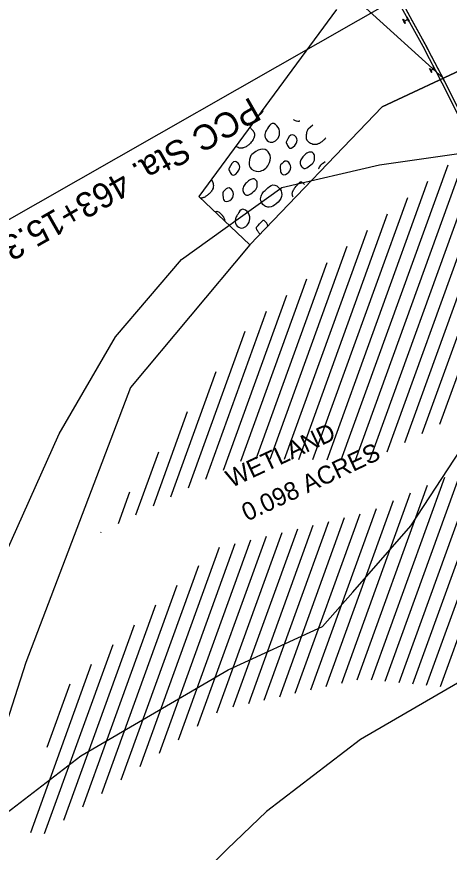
# Model space of a CAD drawing. Extents: x 2355002 to 2355569, y 708374 to 709566.
# Drawn here: x 2355270.5 to 2355318.9, y 709251.3 to 709344.6 of the extents above; entities that cross this region are included whole.
import ezdxf

# ---------------------------------------------------------------- set-up
doc = ezdxf.new("R2010")
doc.units = 0
for name, color, linetype in [('BD_X_Building', 7, 'Continuous'), ('BR_X_Rail_Stl_Det', 7, 'Continuous'), ('BR_X_Slab_Object', 7, 'Continuous'), ('DR_X_Ditch', 7, 'Continuous'), ('HY_X_Water_Edge', 7, 'Continuous'), ('HY_X_Wetland_Area', 7, 'Continuous'), ('PM_X_Edge_Line', 7, 'Continuous'), ('PM_X_Stop_Line', 7, 'Continuous'), ('RD_X_Concrete_Pad', 7, 'Continuous'), ('RD_X_RR_Cells', 7, 'Continuous'), ('SH_Text', 7, 'Continuous'), ('VG_X_Tree_Line_Rt', 7, 'Continuous')]:
    doc.layers.add(name, color=color, linetype=linetype)

msp = doc.modelspace()

# ---------------------------------------------------------------- linework, layer by layer
at = {"layer": 'BR_X_Rail_Stl_Det'}
for points in [[(2355313.802, 709344.05), (2355313.679, 709344.271), (2355313.712, 709344.29), (2355313.815, 709344.106)], [(2355313.856, 709344.031), (2355313.959, 709343.847), (2355313.925, 709343.829), (2355313.802, 709344.05)], [(2355313.855, 709344.095), (2355314.201, 709344.287)], [(2355314.214, 709344.264), (2355313.868, 709344.071)], [(2355314.213, 709344.328), (2355314.111, 709344.511), (2355314.144, 709344.53), (2355314.39, 709344.087), (2355314.357, 709344.068), (2355314.255, 709344.252)], [(2355316.76, 709338.56), (2355316.643, 709338.785), (2355316.676, 709338.802), (2355316.774, 709338.616)], [(2355316.813, 709338.539), (2355316.911, 709338.353), (2355316.877, 709338.335), (2355316.76, 709338.56)], [(2355316.814, 709338.603), (2355317.165, 709338.787)], [(2355317.177, 709338.763), (2355316.826, 709338.58)], [(2355317.178, 709338.827), (2355317.08, 709339.013), (2355317.114, 709339.031), (2355317.348, 709338.582), (2355317.315, 709338.564), (2355317.218, 709338.75)]]:
    msp.add_lwpolyline(points, dxfattribs=at)
for centre, radius, start, end in [((2355104.75, 709227.887), 239.69, 6.23645, 29.69194), ((2355104.75, 709227.887), 240.024, 6.23645, 29.69194), ((2355313.841, 709344.121), 0.0298, 209.0594, 299.0594), ((2355313.882, 709344.045), 0.0298, 119.0594, 209.0594), ((2355314.187, 709344.313), 0.0298, 299.0594, 29.0594), ((2355314.229, 709344.238), 0.0298, 29.0594, 119.0594), ((2355316.8, 709338.63), 0.0298, 207.56539, 297.56539), ((2355316.84, 709338.553), 0.0298, 117.56539, 207.56539), ((2355317.151, 709338.813), 0.0298, 297.56539, 27.56539), ((2355317.191, 709338.737), 0.0298, 27.56539, 117.56539)]:
    msp.add_arc(centre, radius, start, end, dxfattribs=at)
at = {"layer": 'BR_X_Slab_Object'}
msp.add_arc((2355104.75, 709227.887), 240.024, 6.69347, 29.69206, dxfattribs=at)
at = {"layer": 'DR_X_Ditch'}
msp.add_lwpolyline([(2355256.934, 709256.527), (2355268.599, 709283.201), (2355275.266, 709297.997), (2355281.566, 709308.847), (2355288.953, 709317.469), (2355300.165, 709325.51), (2355311.07, 709328.057), (2355320.733, 709329.426)], dxfattribs=at)
at = {"layer": 'HY_X_Water_Edge'}
for points in [[(2355250.911, 709219.998), (2355253.586, 709233.349), (2355257.951, 709241.6), (2355265.075, 709252.406), (2355277.693, 709262.077), (2355294.163, 709271.671), (2355304.717, 709276.5), (2355308.101, 709280.351), (2355314.576, 709287.749), (2355320.15, 709296.253), (2355326.599, 709303.193), (2355329.602, 709308.443), (2355330.306, 709308.794)], [(2355337.752, 709284.561), (2355335.596, 709283.025), (2355327.107, 709277.253), (2355320.964, 709270.848), (2355308.961, 709263.899), (2355298.457, 709255.856), (2355294.044, 709251.65), (2355284.365, 709241.954), (2355272.475, 709233.758), (2355267.361, 709225.229), (2355264.268, 709216.725)]]:
    msp.add_lwpolyline(points, dxfattribs=at)
at = {"layer": 'HY_X_Wetland_Area'}
msp.add_lwpolyline([(2355402.731, 709358.025), (2355392.727, 709358.151), (2355360.724, 709357.63), (2355311.362, 709334.527), (2355296.582, 709319.103), (2355283.234, 709303.179), (2355271.55, 709272.489), (2355265.075, 709252.406)], dxfattribs=at)
at = {"layer": 'PM_X_Edge_Line'}
msp.add_arc((2355104.75, 709227.886), 246.024, 5.4603, 29.69206, dxfattribs=at)
at = {"layer": 'PM_X_Stop_Line'}
msp.add_line((2355303.089, 709332.064), (2355303.619, 709332.506), dxfattribs=at)
msp.add_lwpolyline([(2355306.276, 709345.396), (2355290.879, 709324.489), (2355296.582, 709319.103), (2355311.362, 709334.527), (2355360.724, 709357.63), (2355392.727, 709358.151), (2355391.331, 709364.068), (2355355.637, 709368.498)], dxfattribs=at)
for points in [[(2355302.183, 709332.911), (2355302.123, 709332.899), (2355302.093, 709332.893), (2355302.063, 709332.889), (2355301.807, 709332.903), (2355301.551, 709333.043), (2355301.477, 709333.11)], [(2355296.581, 709332.232), (2355296.657, 709332.157), (2355296.732, 709332.076), (2355296.807, 709331.994), (2355296.879, 709331.913), (2355296.92, 709331.864), (2355296.957, 709331.815), (2355297.016, 709331.712), (2355297.084, 709331.501), (2355297.093, 709331.291), (2355297.077, 709331.19), (2355297.064, 709331.142), (2355297.049, 709331.094), (2355297.005, 709330.982), (2355296.953, 709330.871), (2355296.825, 709330.657), (2355296.661, 709330.453), (2355296.564, 709330.355), (2355296.511, 709330.307), (2355296.484, 709330.283), (2355296.456, 709330.259), (2355296.358, 709330.182), (2355296.259, 709330.115), (2355296.06, 709330.008), (2355295.86, 709329.934), (2355295.758, 709329.908), (2355295.707, 709329.899), (2355295.656, 709329.89), (2355295.401, 709329.905), (2355295.144, 709330.045), (2355295.041, 709330.141)], [(2355298.569, 709332.089), (2355299.078, 709332.66), (2355299.741, 709332.224), (2355299.882, 709331.395), (2355299.458, 709330.728), (2355298.845, 709330.571), (2355298.299, 709331.109), (2355298.337, 709331.717), (2355298.569, 709332.089)], [(2355305.073, 709331.055), (2355305.011, 709330.982), (2355304.948, 709330.913), (2355304.82, 709330.782), (2355304.554, 709330.563), (2355304.279, 709330.403), (2355304.139, 709330.348), (2355304.069, 709330.327), (2355304.033, 709330.319), (2355303.998, 709330.311), (2355303.939, 709330.302), (2355303.878, 709330.297), (2355303.752, 709330.302), (2355303.492, 709330.367), (2355303.24, 709330.51), (2355303.124, 709330.611), (2355303.07, 709330.669), (2355303.044, 709330.7), (2355303.031, 709330.716), (2355303.019, 709330.732), (2355302.99, 709330.773), (2355302.966, 709330.814), (2355302.93, 709330.896), (2355302.898, 709331.061), (2355302.902, 709331.226), (2355302.911, 709331.308), (2355302.921, 709331.39), (2355302.935, 709331.507), (2355302.951, 709331.625), (2355302.974, 709331.742), (2355303.008, 709331.856), (2355303.089, 709332.064)], [(2355300.661, 709330.65), (2355301.358, 709331.402), (2355301.772, 709331.113), (2355301.758, 709330.438), (2355301.014, 709329.905), (2355300.74, 709330.306), (2355300.645, 709330.528), (2355300.661, 709330.65)], [(2355296.683, 709329.066), (2355297.248, 709329.537), (2355298.303, 709329.74), (2355298.839, 709329.102), (2355298.672, 709328.063), (2355297.592, 709327.313), (2355296.612, 709327.734), (2355296.515, 709328.391), (2355296.602, 709328.857), (2355296.683, 709329.066)], [(2355302.262, 709328.606), (2355302.609, 709329.044), (2355303.105, 709329.404), (2355303.556, 709329.436), (2355303.79, 709329.097), (2355303.732, 709328.414), (2355303.266, 709327.931), (2355302.624, 709327.644), (2355302.286, 709327.962), (2355302.21, 709328.368), (2355302.262, 709328.606)], [(2355294.255, 709327.652), (2355294.952, 709328.403), (2355295.365, 709328.115), (2355295.351, 709327.44), (2355294.608, 709326.906), (2355294.333, 709327.308), (2355294.238, 709327.53), (2355294.255, 709327.652)], [(2355300.016, 709328.034), (2355300.66, 709328.458), (2355301.127, 709327.952), (2355300.942, 709327.215), (2355300.194, 709326.99), (2355299.99, 709327.438), (2355299.957, 709327.783), (2355300.016, 709328.034)], [(2355304.266, 709327.596), (2355304.29, 709327.648), (2355304.317, 709327.699), (2355304.346, 709327.75), (2355304.377, 709327.8), (2355304.522, 709328.012), (2355304.602, 709328.105), (2355304.646, 709328.148), (2355304.694, 709328.187), (2355304.828, 709328.289)], [(2355292.28, 709326.391), (2355292.324, 709326.322), (2355292.365, 709326.25), (2355292.401, 709326.177), (2355292.417, 709326.14), (2355292.433, 709326.104), (2355292.455, 709326.042), (2355292.474, 709325.979), (2355292.499, 709325.85), (2355292.497, 709325.583), (2355292.421, 709325.316), (2355292.354, 709325.188), (2355292.312, 709325.125), (2355292.29, 709325.095), (2355292.266, 709325.065), (2355292.14, 709324.921), (2355292.012, 709324.79), (2355291.745, 709324.568), (2355291.468, 709324.407), (2355291.327, 709324.352), (2355291.256, 709324.331), (2355291.185, 709324.314), (2355291.078, 709324.301)], [(2355295.856, 709325.608), (2355296.203, 709326.046), (2355296.699, 709326.405), (2355297.149, 709326.438), (2355297.383, 709326.098), (2355297.325, 709325.416), (2355296.86, 709324.933), (2355296.218, 709324.646), (2355295.879, 709324.964), (2355295.803, 709325.37), (2355295.856, 709325.608)], [(2355293.61, 709325.035), (2355294.254, 709325.46), (2355294.721, 709324.953), (2355294.536, 709324.217), (2355293.787, 709323.992), (2355293.583, 709324.439), (2355293.551, 709324.785), (2355293.61, 709325.035)], [(2355298.408, 709325.281), (2355299.167, 709325.803), (2355299.958, 709325.334), (2355300.128, 709324.516), (2355299.534, 709323.68), (2355298.735, 709323.312), (2355298.223, 709323.466), (2355297.78, 709324.241), (2355297.97, 709324.801), (2355298.287, 709325.189), (2355298.422, 709325.291)], [(2355301.42, 709324.45), (2355301.398, 709324.489), (2355301.388, 709324.51), (2355301.378, 709324.53), (2355301.363, 709324.567), (2355301.35, 709324.605), (2355301.331, 709324.683), (2355301.323, 709324.843), (2355301.352, 709324.998), (2355301.379, 709325.071), (2355301.396, 709325.106), (2355301.415, 709325.139), (2355301.648, 709325.511)], [(2355301.648, 709325.511), (2355302.157, 709326.082), (2355302.17, 709326.095), (2355302.183, 709326.106), (2355302.211, 709326.123), (2355302.27, 709326.136), (2355302.4, 709326.093), (2355302.538, 709325.982), (2355302.606, 709325.911), (2355302.672, 709325.834)], [(2355292.703, 709322.766), (2355292.76, 709322.805), (2355292.784, 709322.819), (2355292.808, 709322.831), (2355292.856, 709322.845), (2355292.955, 709322.843), (2355293.155, 709322.74), (2355293.356, 709322.552), (2355293.455, 709322.444), (2355293.504, 709322.39), (2355293.552, 709322.336), (2355293.581, 709322.303), (2355293.608, 709322.268), (2355293.654, 709322.198), (2355293.723, 709322.054), (2355293.76, 709321.907), (2355293.767, 709321.833), (2355293.768, 709321.761)], [(2355295.242, 709322.512), (2355295.751, 709323.084), (2355296.413, 709322.647), (2355296.555, 709321.818), (2355296.131, 709321.151), (2355295.518, 709320.995), (2355294.972, 709321.532), (2355295.009, 709322.14), (2355295.242, 709322.512)], [(2355297.334, 709321.073), (2355298.031, 709321.825), (2355298.042, 709321.835), (2355298.053, 709321.844), (2355298.077, 709321.854), (2355298.127, 709321.853), (2355298.237, 709321.783), (2355298.346, 709321.662), (2355298.397, 709321.597), (2355298.421, 709321.565), (2355298.444, 709321.536), (2355298.515, 709321.41), (2355298.547, 709321.275)], [(2355297.688, 709320.326), (2355297.686, 709320.328), (2355297.614, 709320.408), (2355297.543, 709320.507), (2355297.476, 709320.617), (2355297.444, 709320.673), (2355297.412, 709320.729), (2355297.346, 709320.838), (2355297.317, 709320.952), (2355297.325, 709321.013), (2355297.334, 709321.073)]]:
    msp.add_spline(points, degree=3, dxfattribs=at)
at = {"layer": 'RD_X_Concrete_Pad'}
msp.add_line((2355304.815, 709328.279), (2355305.003, 709328.41), dxfattribs=at)
msp.add_spline([(2355298.04, 709334.078), (2355298.004, 709334.004), (2355297.961, 709333.931), (2355297.914, 709333.86), (2355297.889, 709333.827), (2355297.876, 709333.81), (2355297.863, 709333.794), (2355297.834, 709333.76), (2355297.801, 709333.726), (2355297.726, 709333.662), (2355297.6, 709333.578), (2355297.556, 709333.555)], degree=3, dxfattribs=at)
at = {"layer": 'RD_X_RR_Cells'}
for p, q in [((2355315.854, 709298.054), (2355329.079, 709334.549)), ((2355313.888, 709297.031), (2355327.133, 709333.581)), ((2355311.922, 709296.008), (2355325.187, 709332.614)), ((2355309.983, 709295.062), (2355323.241, 709331.647)), ((2355308.395, 709295.082), (2355320.989, 709329.837)), ((2355306.806, 709295.101), (2355318.736, 709328.022)), ((2355305.218, 709295.12), (2355316.483, 709326.206)), ((2355303.629, 709295.139), (2355314.23, 709324.391)), ((2355302.041, 709295.159), (2355311.976, 709322.576)), ((2355300.453, 709295.178), (2355309.723, 709320.761)), ((2355298.864, 709295.197), (2355307.47, 709318.946)), ((2355297.276, 709295.216), (2355305.217, 709317.131)), ((2355317.82, 709299.077), (2355324.186, 709316.645)), ((2355295.585, 709294.953), (2355302.964, 709315.315)), ((2355293.629, 709293.958), (2355300.71, 709313.5)), ((2355291.673, 709292.964), (2355298.457, 709311.685)), ((2355289.717, 709291.969), (2355296.054, 709309.456)), ((2355287.761, 709290.974), (2355292.835, 709304.976)), ((2355285.805, 709289.979), (2355289.616, 709300.497)), ((2355317.882, 709269.808), (2355327.914, 709297.492)), ((2355316.341, 709269.956), (2355326.004, 709296.625)), ((2355283.849, 709288.984), (2355286.398, 709296.017)), ((2355314.799, 709270.104), (2355324.095, 709295.757)), ((2355313.257, 709270.252), (2355322.185, 709294.89)), ((2355311.715, 709270.4), (2355320.275, 709294.022)), ((2355310.173, 709270.548), (2355318.365, 709293.155)), ((2355308.58, 709270.555), (2355316.456, 709292.288)), ((2355281.893, 709287.989), (2355283.179, 709291.538)), ((2355306.848, 709270.178), (2355314.546, 709291.42)), ((2355305.116, 709269.8), (2355312.636, 709290.553)), ((2355301.651, 709269.045), (2355308.905, 709289.062)), ((2355303.383, 709269.422), (2355310.726, 709289.686)), ((2355298.187, 709268.289), (2355305.416, 709288.24)), ((2355299.919, 709268.667), (2355307.161, 709288.651)), ((2355294.722, 709267.534), (2355301.927, 709287.417)), ((2355296.454, 709267.912), (2355303.672, 709287.829)), ((2355279.937, 709286.995), (2355279.96, 709287.058)), ((2355288.605, 709263.863), (2355296.694, 709286.184)), ((2355290.744, 709265.361), (2355298.438, 709286.595)), ((2355292.882, 709266.858), (2355300.183, 709287.006)), ((2355284.329, 709260.867), (2355293.205, 709285.362)), ((2355286.467, 709262.365), (2355294.949, 709285.773)), ((2355282.191, 709259.37), (2355290.866, 709283.309)), ((2355280.053, 709257.872), (2355288.472, 709281.107)), ((2355277.914, 709256.374), (2355286.079, 709278.905)), ((2355275.776, 709254.876), (2355283.685, 709276.703)), ((2355273.638, 709253.379), (2355281.292, 709274.501)), ((2355272.09, 709253.51), (2355278.899, 709272.299)), ((2355273.938, 709263.013), (2355276.505, 709270.097))]:
    msp.add_line(p, q, dxfattribs=at)
at = {"layer": 'SH_Text'}
msp.add_line((2355328.027, 709355.2), (2355266.135, 709319.909), dxfattribs=at)
at = {"layer": 'VG_X_Tree_Line_Rt'}
msp.add_line((2355318.172, 709337.714), (2355309.147, 709345.912), dxfattribs=at)

# ---------------------------------------------------------------- texts
at = {"layer": 'BD_X_Building'}
for s, p in [('WETLAND', (2355294.511, 709291.953)), ('0.098 ACRES', (2355296.266, 709288.204))]:
    msp.add_text(s, height=2, rotation=25.08075, dxfattribs=at).set_placement(p)
at = {"layer": 'SH_Text'}
msp.add_text('PCC Sta. 463+15.39', height=2.8, rotation=209.69206, dxfattribs=at).set_placement((2355296.683, 709335.668))

doc.saveas('drawing.dxf')
